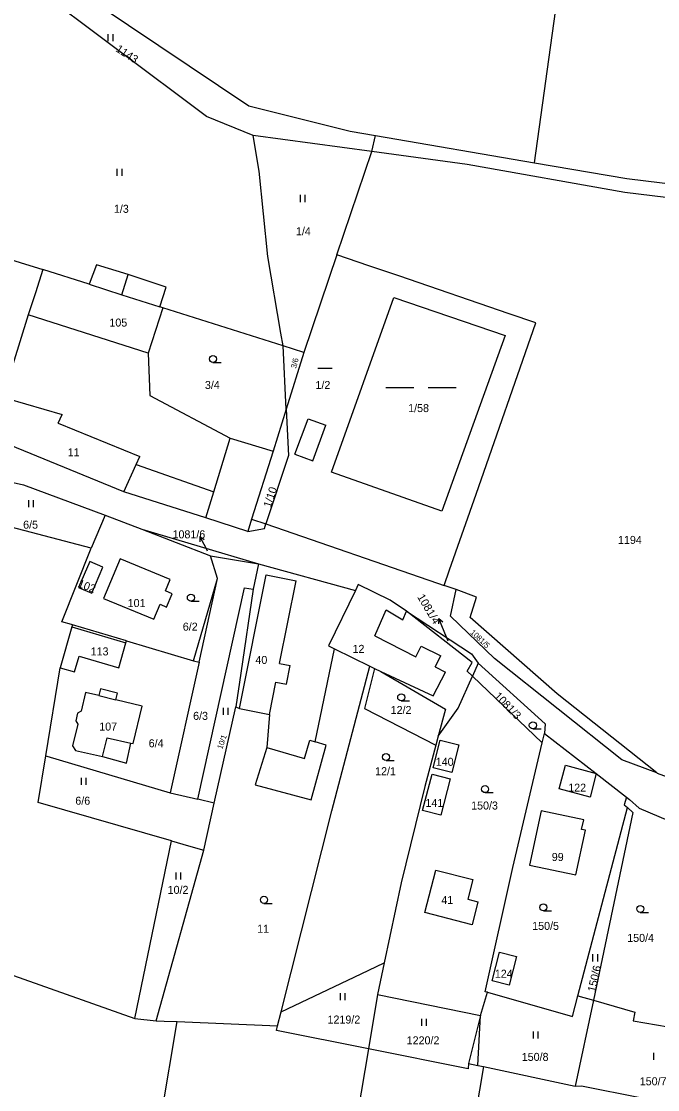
# Model space of a CAD drawing. Extents: x -746176 to -739709, y -1127410 to -1124482.
# Drawn here: x -742146.3 to -742011.1, y -1126433.2 to -1126206.3 of the extents above; entities that cross this region are included whole.
import ezdxf

# ---------------------------------------------------------------- set-up
doc = ezdxf.new("R2010")
doc.units = 0
for name, color, linetype in [('Hranice parcel', 7, 'Continuous'), ('Parcelní čísla', 7, 'Continuous'), ('Pop  PČ popisy', 7, 'Continuous'), ('Vnitřní kresba', 7, 'Continuous'), ('Značky kultur', 7, 'Continuous')]:
    doc.layers.add(name, color=color, linetype=linetype)

msp = doc.modelspace()

# ---------------------------------------------------------------- linework, layer by layer
at = {"layer": 'Hranice parcel'}
for p, q in [((-742037.23, -1126236.37), (-742032.39, -1126201.61)), ((-742071.8, -1126233.98), (-742097.01, -1126230.58)), ((-742071.8, -1126233.98), (-742071.02, -1126230.56)), ((-742071.02, -1126230.56), (-742037.23, -1126236.37)), ((-742079.26, -1126255.9), (-742071.8, -1126233.98)), ((-742152.42, -1126255.73), (-742141.7, -1126259.03)), ((-742079.26, -1126255.9), (-742086.23, -1126276.66)), ((-742116.22, -1126267.19), (-742119.31, -1126276.84)), ((-742090.65, -1126275.25), (-742116.22, -1126267.19)), ((-742119.31, -1126276.84), (-742144.79, -1126268.68)), ((-742090.65, -1126275.25), (-742091.11, -1126272.55)), ((-742089.98, -1126288.73), (-742090.65, -1126275.25)), ((-742086.23, -1126276.66), (-742090.65, -1126275.25)), ((-742086.23, -1126276.66), (-742089.98, -1126288.73)), ((-742089.98, -1126288.73), (-742092.74, -1126297.6)), ((-742128.49, -1126311.19), (-742131.46, -1126318.2)), ((-742128.49, -1126311.19), (-742120.66, -1126314.22)), ((-742131.46, -1126318.2), (-742148.42, -1126313.8)), ((-742120.66, -1126314.22), (-742106.07, -1126319.87)), ((-742120.66, -1126314.22), (-742095.86, -1126321.55)), ((-742137.67, -1126333.86), (-742131.46, -1126318.2)), ((-742106.07, -1126319.87), (-742095.86, -1126321.55)), ((-742095.86, -1126321.55), (-742097.02, -1126326.92)), ((-742095.86, -1126321.55), (-742075.26, -1126327.22)), ((-742053.88, -1126327.04), (-742056.42, -1126326.16)), ((-742135.58, -1126334.46), (-742137.67, -1126333.86)), ((-742135.39, -1126334.52), (-742135.58, -1126334.46)), ((-742123.93, -1126337.94), (-742135.39, -1126334.52)), ((-742079.74, -1126339.61), (-742072.2, -1126343.28)), ((-742108.51, -1126342.48), (-742114.63, -1126370.19)), ((-742072.2, -1126343.28), (-742071.19, -1126343.77)), ((-742049.16, -1126342.68), (-742050.39, -1126345.41)), ((-742141.07, -1126362.36), (-742138.05, -1126343.65)), ((-742035.57, -1126359.6), (-742050.39, -1126345.41)), ((-742105.28, -1126372.36), (-742100.72, -1126351.93)), ((-742056.12, -1126352.45), (-742057.69, -1126358.14)), ((-742057.69, -1126358.14), (-742058.21, -1126360.09)), ((-742035.57, -1126359.6), (-742035.1, -1126357.57)), ((-742058.21, -1126360.09), (-742060.53, -1126368.87)), ((-742141.07, -1126362.36), (-742140.82, -1126362.44)), ((-742140.82, -1126362.44), (-742114.63, -1126370.19)), ((-742114.63, -1126370.19), (-742108.8, -1126371.54)), ((-742105.28, -1126372.36), (-742108.8, -1126371.54)), ((-742107.51, -1126382.37), (-742105.28, -1126372.36)), ((-742028.01, -1126413.28), (-742017.48, -1126373.34)), ((-742122.15, -1126418.14), (-742114.39, -1126380.39)), ((-742114.39, -1126380.39), (-742110.73, -1126381.44)), ((-742110.73, -1126381.44), (-742107.51, -1126382.37)), ((-742117.61, -1126418.59), (-742107.51, -1126382.37)), ((-742160.44, -1126404.55), (-742122.15, -1126418.14)), ((-742069.18, -1126406.33), (-742070.6, -1126413.05)), ((-742070.6, -1126413.05), (-742072.53, -1126424.54)), ((-742070.6, -1126413.05), (-742048.68, -1126417.48)), ((-742048.68, -1126417.48), (-742047.21, -1126412.52)), ((-742028.01, -1126413.28), (-742024.68, -1126414.24)), ((-742024.68, -1126414.24), (-742028.56, -1126432.53)), ((-742122.15, -1126418.14), (-742117.61, -1126418.59)), ((-742091.83, -1126419.68), (-742091.05, -1126416.72)), ((-742048.68, -1126417.48), (-742051.23, -1126427.71)), ((-742113.18, -1126418.78), (-742091.83, -1126419.68)), ((-742072.53, -1126424.54), (-742085.13, -1126499.75)), ((-742048.06, -1126428.34), (-742062.27, -1126510.43)), ((-742048.06, -1126428.34), (-742028.56, -1126432.53))]:
    msp.add_line(p, q, dxfattribs=at)
for points in [[(-742159.24, -1126187.68), (-742155.35, -1126185.74), (-742097.93, -1126224.3), (-742076.36, -1126229.64), (-742071.02, -1126230.56)], [(-742097.01, -1126230.58), (-742106.9, -1126226.55), (-742144.78, -1126198.17), (-742157.57, -1126188.32), (-742159.24, -1126187.68)], [(-742091.11, -1126272.55), (-742093.87, -1126256.26), (-742095.72, -1126238.15), (-742097.01, -1126230.58)], [(-741979.16, -1126247.44), (-742018.02, -1126242.67), (-742051.56, -1126236.78), (-742071.8, -1126233.98)], [(-742037.23, -1126236.37), (-742017.58, -1126239.71), (-741978.86, -1126244.46), (-741935.37, -1126247.86), (-741906.75, -1126240.11), (-741905.97, -1126243.01), (-741935.09, -1126250.9), (-741979.16, -1126247.44)], [(-742056.42, -1126326.16), (-742055.26, -1126322.85), (-742049.63, -1126306.73), (-742036.93, -1126270.38), (-742042.58, -1126268.45), (-742066.08, -1126260.42), (-742072.41, -1126258.25), (-742079.26, -1126255.9)], [(-742141.7, -1126259.03), (-742143.26, -1126264), (-742144.79, -1126268.68)], [(-742116.22, -1126267.19), (-742116.82, -1126267), (-742115.46, -1126262.77), (-742123.54, -1126260.09), (-742130.31, -1126258.08), (-742131.85, -1126262.18), (-742141.7, -1126259.03)], [(-742080.37, -1126302.09), (-742067.12, -1126265.01), (-742043.47, -1126273.03), (-742056.95, -1126310.39), (-742080.37, -1126302.09)], [(-742144.79, -1126268.68), (-742148.06, -1126279.2), (-742152.35, -1126276.44)], [(-742119.31, -1126276.84), (-742118.96, -1126285.81), (-742101.9, -1126294.87), (-742092.74, -1126297.6)], [(-742089.98, -1126288.73), (-742089.5, -1126298.57), (-742094.3, -1126313.08)], [(-742098.16, -1126314.66), (-742107.1, -1126311.81), (-742124.49, -1126306.28), (-742152.92, -1126294.67), (-742154.48, -1126293.27)], [(-742092.74, -1126297.6), (-742097.33, -1126312.04), (-742098.16, -1126314.66)], [(-742156.3, -1126302.44), (-742145.81, -1126304.8), (-742128.49, -1126311.19)], [(-742098.16, -1126314.66), (-742094.61, -1126314.04), (-742094.3, -1126313.08)], [(-742094.3, -1126313.08), (-742057.82, -1126325.67), (-742056.42, -1126326.16)], [(-742116.8, -1126330.16), (-742115.42, -1126330.73), (-742114.25, -1126327.9), (-742115.63, -1126327.32), (-742114.63, -1126324.9), (-742125.3, -1126320.48), (-742128.78, -1126328.9), (-742118.11, -1126333.31), (-742116.8, -1126330.16)], [(-742108.51, -1126342.48), (-742104.56, -1126324.65), (-742106.07, -1126319.87)], [(-742131.3, -1126327.79), (-742128.95, -1126322.27), (-742131.75, -1126321.08), (-742134.1, -1126326.6), (-742131.3, -1126327.79)], [(-742108.8, -1126371.54), (-742098.88, -1126326.64), (-742097.02, -1126326.92)], [(-742097.02, -1126326.92), (-742099.61, -1126344.81), (-742100.72, -1126351.93)], [(-742075.26, -1126327.22), (-742081, -1126339.01), (-742079.74, -1126339.61)], [(-742064.45, -1126331.63), (-742067.87, -1126329.27), (-742074.66, -1126325.97), (-742075.26, -1126327.22)], [(-742011.25, -1126365.95), (-742018.63, -1126363.2), (-742045.74, -1126341.65), (-742055.06, -1126332.67), (-742053.88, -1126327.04)], [(-742011.25, -1126365.95), (-742032.44, -1126349.16), (-742050.91, -1126332.94), (-742049.54, -1126328.65), (-742053.88, -1126327.04)], [(-742050.39, -1126345.41), (-742051.51, -1126344.33), (-742050.48, -1126342.5), (-742064.45, -1126331.63)], [(-742064.45, -1126331.63), (-742050.58, -1126340.65), (-742049.16, -1126342.68)], [(-742135.39, -1126334.52), (-742135.51, -1126334.93), (-742138.05, -1126343.65)], [(-742138.05, -1126343.65), (-742134.99, -1126344.48), (-742134.01, -1126341.18), (-742125.58, -1126343.66), (-742124.04, -1126338.33), (-742123.93, -1126337.94)], [(-742123.93, -1126337.94), (-742109.71, -1126342.16), (-742108.51, -1126342.48)], [(-742100.72, -1126351.93), (-742099.9, -1126352.31), (-742093.57, -1126353.58), (-742094.13, -1126360.58), (-742096.61, -1126368.48), (-742084.66, -1126371.69), (-742081.5, -1126360.05), (-742083.81, -1126359.38), (-742079.74, -1126339.61)], [(-742091.05, -1126416.72), (-742080.28, -1126374.02), (-742072.2, -1126343.28)], [(-742049.16, -1126342.68), (-742034.95, -1126355.55), (-742035.1, -1126357.57)], [(-742071.19, -1126343.77), (-742073.35, -1126352.28), (-742058.21, -1126360.09)], [(-742071.19, -1126343.77), (-742069.89, -1126344.4), (-742056.12, -1126352.45)], [(-742057.69, -1126358.14), (-742053.45, -1126352.23), (-742050.39, -1126345.41)], [(-742134.78, -1126361.18), (-742129.01, -1126362.5), (-742123.94, -1126363.89), (-742123.02, -1126359.67), (-742122.51, -1126359.71), (-742120.59, -1126351.76), (-742126.19, -1126350.41), (-742125.85, -1126349), (-742129.47, -1126348.12), (-742129.81, -1126349.53), (-742132.62, -1126348.87), (-742133.58, -1126352.84), (-742134.31, -1126353.29), (-742134.7, -1126354.88), (-742134.27, -1126355.59), (-742135.37, -1126360.18), (-742134.78, -1126361.18)], [(-742054.77, -1126365.88), (-742058.74, -1126364.92), (-742057.24, -1126358.99), (-742053.27, -1126359.99), (-742054.77, -1126365.88)], [(-742035.1, -1126357.57), (-742024.1, -1126366.11), (-742017.65, -1126371.11)], [(-742047.21, -1126412.52), (-742047.73, -1126412.44), (-742041.81, -1126386.09), (-742035.57, -1126359.6)], [(-742114.39, -1126380.39), (-742142.67, -1126372.26), (-742141.07, -1126362.36)], [(-742024.1, -1126366.11), (-742025.41, -1126371.14), (-742032, -1126369.36), (-742030.67, -1126364.32), (-742024.1, -1126366.11)], [(-741995.94, -1126371.66), (-741996.93, -1126371.29), (-742011.08, -1126366.08), (-742011.25, -1126365.95)], [(-742058.98, -1126366.22), (-742055.17, -1126367.22), (-742057.16, -1126374.93), (-742061.01, -1126373.94), (-742058.98, -1126366.22)], [(-742060.53, -1126368.87), (-742065.58, -1126389.34), (-742069.18, -1126406.33)], [(-742017.65, -1126371.11), (-742018.15, -1126372.75), (-742017.48, -1126373.34)], [(-742017.65, -1126371.11), (-742017.02, -1126371.6), (-742014.99, -1126373.44), (-741986.71, -1126385.43)], [(-742026.38, -1126378.16), (-742027.21, -1126377.99), (-742026.77, -1126375.94), (-742035.82, -1126374), (-742038.29, -1126385.53), (-742028.41, -1126387.64), (-742026.38, -1126378.16)], [(-742017.48, -1126373.34), (-742016.3, -1126374.36), (-742024.68, -1126414.24)], [(-742051.38, -1126392.8), (-742049.23, -1126393.33), (-742050.47, -1126398.22), (-742060.55, -1126395.61), (-742058.21, -1126386.6), (-742050.31, -1126388.63), (-742051.38, -1126392.8)], [(-742044.65, -1126404.04), (-742041.06, -1126404.95), (-742042.6, -1126411.06), (-742046.19, -1126410.15), (-742044.65, -1126404.04)], [(-742091.05, -1126416.72), (-742074.03, -1126408.64), (-742069.18, -1126406.33)], [(-742047.21, -1126412.52), (-742029.18, -1126417.71), (-742028.01, -1126413.28)], [(-742024.68, -1126414.24), (-742015.91, -1126416.77), (-742016.26, -1126418.65), (-742006.36, -1126420.29)], [(-742130.78, -1126507.86), (-742119.81, -1126458.38), (-742113.18, -1126418.78)], [(-742117.61, -1126418.59), (-742115.93, -1126418.66), (-742113.18, -1126418.78)], [(-742072.53, -1126424.54), (-742092.04, -1126420.67), (-742091.83, -1126419.68)], [(-742051.23, -1126427.71), (-742051.35, -1126428.82), (-742072.53, -1126424.54)], [(-742051.23, -1126427.71), (-742049.27, -1126428.1), (-742048.06, -1126428.34)], [(-742028.56, -1126432.53), (-742027.22, -1126432.46), (-742014.43, -1126435)]]:
    msp.add_lwpolyline(points, dxfattribs=at)
at = {"layer": 'Pop  PČ popisy'}
for p, q in [((-742106.94, -1126318.4), (-742108.349, -1126315.75)), ((-742108.349, -1126315.75), (-742107.437, -1126316.399)), ((-742108.349, -1126315.75), (-742108.321, -1126316.87)), ((-742106.68, -1126318.88), (-742106.94, -1126318.4)), ((-742057.554, -1126333.158), (-742057.643, -1126334.274)), ((-742056.43, -1126335.94), (-742057.554, -1126333.158)), ((-742057.554, -1126333.158), (-742056.715, -1126333.898)), ((-742055.59, -1126337.98), (-742056.43, -1126335.94))]:
    msp.add_line(p, q, dxfattribs=at)
at = {"layer": 'Vnitřní kresba'}
for p, q in [((-742124.92, -1126264.4), (-742123.54, -1126260.09)), ((-742131.85, -1126262.18), (-742124.92, -1126264.4)), ((-742124.92, -1126264.4), (-742116.82, -1126267)), ((-742149.27, -1126286.44), (-742137.57, -1126289.85)), ((-742138.41, -1126291.71), (-742137.57, -1126289.85)), ((-742088.12, -1126298.3), (-742085.35, -1126290.74)), ((-742085.35, -1126290.74), (-742081.58, -1126292.13)), ((-742138.41, -1126291.71), (-742121.1, -1126298.77)), ((-742084.35, -1126299.68), (-742081.58, -1126292.13)), ((-742105.39, -1126306.24), (-742101.9, -1126294.87)), ((-742121.85, -1126300.43), (-742121.1, -1126298.77)), ((-742088.12, -1126298.3), (-742084.35, -1126299.68)), ((-742124.49, -1126306.28), (-742121.85, -1126300.43)), ((-742121.85, -1126300.43), (-742105.39, -1126306.24)), ((-742107.1, -1126311.81), (-742105.39, -1126306.24)), ((-742097.33, -1126312.04), (-742094.3, -1126313.08)), ((-742109.71, -1126342.16), (-742104.56, -1126324.65)), ((-742099.9, -1126352.31), (-742094.21, -1126323.93)), ((-742094.21, -1126323.93), (-742087.88, -1126325.2)), ((-742091.39, -1126342.7), (-742087.88, -1126325.2)), ((-742071.15, -1126336.85), (-742068.73, -1126331.35)), ((-742068.73, -1126331.35), (-742065.22, -1126333.43)), ((-742065.22, -1126333.43), (-742064.45, -1126331.63)), ((-742135.51, -1126334.93), (-742124.04, -1126338.33)), ((-742071.15, -1126336.85), (-742062.44, -1126341.34)), ((-742062.44, -1126341.34), (-742061.28, -1126339.07)), ((-742061.28, -1126339.07), (-742057.13, -1126341.13)), ((-742058.33, -1126343.46), (-742057.13, -1126341.13)), ((-742091.39, -1126342.7), (-742089.14, -1126343.15)), ((-742089.94, -1126347.14), (-742089.14, -1126343.15)), ((-742058.33, -1126343.46), (-742056.16, -1126344.57)), ((-742069.89, -1126344.4), (-742058.75, -1126349.59)), ((-742058.75, -1126349.59), (-742056.16, -1126344.57)), ((-742093.57, -1126353.58), (-742092.19, -1126346.69)), ((-742092.19, -1126346.69), (-742089.94, -1126347.14)), ((-742129.81, -1126349.53), (-742126.19, -1126350.41)), ((-742129.01, -1126362.5), (-742128.01, -1126358.52)), ((-742128.01, -1126358.52), (-742123.02, -1126359.67)), ((-742086.12, -1126362.9), (-742085, -1126359.04)), ((-742085, -1126359.04), (-742083.81, -1126359.38)), ((-742094.13, -1126360.58), (-742086.12, -1126362.9)), ((-742049.27, -1126428.1), (-742048.68, -1126417.48))]:
    msp.add_line(p, q, dxfattribs=at)
at = {"layer": 'Značky kultur'}
for p, q in [((-742127.791, -1126210.53), (-742127.791, -1126209.03)), ((-742126.79, -1126210.53), (-742126.79, -1126209.03)), ((-742125.881, -1126239.16), (-742125.881, -1126237.66)), ((-742124.88, -1126239.16), (-742124.88, -1126237.66)), ((-742086.941, -1126244.72), (-742086.941, -1126243.22)), ((-742085.94, -1126244.72), (-742085.94, -1126243.22)), ((-742105.543, -1126278.8), (-742103.793, -1126278.8)), ((-742083.238, -1126280.01), (-742080.238, -1126280.01)), ((-742068.849, -1126284.1), (-742062.849, -1126284.1)), ((-742059.849, -1126284.1), (-742053.849, -1126284.1)), ((-742144.691, -1126309.55), (-742144.691, -1126308.05)), ((-742143.69, -1126309.55), (-742143.69, -1126308.05)), ((-742110.243, -1126329.5), (-742108.493, -1126329.5)), ((-742103.341, -1126353.64), (-742103.341, -1126352.14)), ((-742102.34, -1126353.64), (-742102.34, -1126352.14)), ((-742065.543, -1126350.67), (-742063.793, -1126350.67)), ((-742037.573, -1126356.61), (-742035.823, -1126356.61)), ((-742068.773, -1126363.34), (-742067.023, -1126363.34)), ((-742133.521, -1126368.52), (-742133.521, -1126367.02)), ((-742132.52, -1126368.52), (-742132.52, -1126367.02)), ((-742047.733, -1126370.16), (-742045.983, -1126370.16)), ((-742113.391, -1126388.6), (-742113.391, -1126387.1)), ((-742112.39, -1126388.6), (-742112.39, -1126387.1)), ((-742094.713, -1126393.67), (-742092.963, -1126393.67)), ((-742035.333, -1126395.27), (-742033.583, -1126395.27)), ((-742014.743, -1126395.61), (-742012.993, -1126395.61)), ((-742024.801, -1126405.99), (-742024.801, -1126404.49)), ((-742023.8, -1126405.99), (-742023.8, -1126404.49)), ((-742078.481, -1126414.25), (-742078.481, -1126412.75)), ((-742077.48, -1126414.25), (-742077.48, -1126412.75)), ((-742061.181, -1126419.71), (-742061.181, -1126418.21)), ((-742060.18, -1126419.71), (-742060.18, -1126418.21)), ((-742037.451, -1126422.4), (-742037.451, -1126420.9)), ((-742036.45, -1126422.4), (-742036.45, -1126420.9)), ((-742011.861, -1126426.93), (-742011.861, -1126425.43))]:
    msp.add_line(p, q, dxfattribs=at)
for centre in [(-742105.543, -1126278.05), (-742110.243, -1126328.75), (-742065.543, -1126349.92), (-742037.573, -1126355.86), (-742068.773, -1126362.59), (-742047.733, -1126369.41), (-742094.713, -1126392.92), (-742035.333, -1126394.52), (-742014.743, -1126394.86)]:
    msp.add_circle(centre, 0.75, dxfattribs=at)

# ---------------------------------------------------------------- texts
at = {"layer": 'Parcelní čísla'}
for s, height, rotation, p in [('1143', 1.7, 327, (-742126.385, -1126212.597)), ('3/6', 1.19, 76, (-742087.872, -1126280.143)), ('1/10', 1.7, 72, (-742093.271, -1126309.762)), ('102', 1.7, 339, (-742134.408, -1126326.405)), ('1081/4', 1.7, 301, (-742062.208, -1126328.597)), ('1081/5', 1.19, 317, (-742050.975, -1126336.265)), ('1081/3', 1.7, 314, (-742045.927, -1126349.762)), ('10/1', 1.19, 71, (-742103.587, -1126361.023)), ('150/6', 1.7, 77, (-742024.325, -1126412.623))]:
    msp.add_text(s, height=height, rotation=rotation, dxfattribs=at).set_placement(p)
for s, p in [('1/3', (-742126.6, -1126247.01)), ('1/4', (-742087.918, -1126251.76)), ('105', (-742127.56, -1126271.17)), ('3/4', (-742107.26, -1126284.42)), ('1/2', (-742083.768, -1126284.43)), ('1/58', (-742064.071, -1126289.33)), ('11', (-742136.422, -1126298.72)), ('6/5', (-742145.888, -1126314.09)), ('1081/6', (-742114.141, -1126316.143)), ('1194', (-742019.477, -1126317.33)), ('101', (-742123.674, -1126330.74)), ('6/2', (-742111.958, -1126335.75)), ('12', (-742075.892, -1126340.47)), ('113', (-742131.54, -1126341.01)), ('40', (-742096.532, -1126342.82)), ('12/2', (-742067.791, -1126353.46)), ('6/3', (-742109.768, -1126354.7)), ('107', (-742129.72, -1126356.97)), ('6/4', (-742119.208, -1126360.52)), ('140', (-742058.204, -1126364.45)), ('12/1', (-742071.091, -1126366.45)), ('122', (-742030.054, -1126369.95)), ('6/6', (-742134.8, -1126372.72)), ('141', (-742060.394, -1126373.18)), ('150/3', (-742050.683, -1126373.74)), ('99', (-742033.552, -1126384.67)), ('10/2', (-742115.18, -1126391.65)), ('41', (-742057.022, -1126393.81)), ('150/5', (-742037.713, -1126399.31)), ('11', (-742096.162, -1126399.92)), ('150/4', (-742017.523, -1126401.86)), ('124', (-742045.654, -1126409.47)), ('1219/2', (-742081.205, -1126419.2)), ('1220/2', (-742064.385, -1126423.62)), ('150/8', (-742039.933, -1126427.13)), ('150/7', (-742014.853, -1126432.31))]:
    msp.add_text(s, height=1.7, dxfattribs=at).set_placement(p)

doc.saveas('drawing.dxf')
